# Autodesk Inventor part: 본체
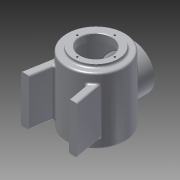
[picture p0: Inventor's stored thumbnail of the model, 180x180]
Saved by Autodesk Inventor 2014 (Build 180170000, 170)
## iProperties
Created: 2015-01
Part Number: 본체
Material: 알루미늄 6061
Document SubType Name: Modeling
Designer: Administrator
Density: 2.71 g/cm^3
Appearance: 알루미늄 - 평지
Mass: 1021.13 g
Surface Area: 1060.37 cm^2
Volume: 376.8 cm^3
Author: Administrator
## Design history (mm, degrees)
sketch "스케치1"
  geometry: L1 (-34, -80)-(-27.282, -41.901); L2 (-48, -80)-(-39.336, -30.865); L3 (-48, -80)-(-34, -80); L4 (0, 50)-(0, -50); A1 r 50 centre (0, 0) between (0, 50) and (-39.336, -30.865); A2 r 50 centre (0, 0) between (-27.282, -41.901) and (0, -50); 1 further point
  constraints: 8 end point, 4 point on circle, 2 centre point, 1 coincident, 1 horizontal, 1 parallel, 1 perpendicular
  dimensions: "d8" = 50 radius of A2; "d9" = 50 radius of A1; "d12" = 13.78731 distance between parallel lines of L1 L2; "d15" = 19.59161 distance from line of point (0, 0) L1; "d16" = 80 distance from line of point (0, 0) L3; "d33" = 10 deg angle of L4 L1; "d34" = 0 distance from line of point (0, 0) L4
extrude "돌출1" new body sketch "스케치1" distance "d17" = 40; taper "d18" = 0 deg
sketch "스케치7"
  geometry: L1 (0, -50)-(0, 50) reference; L2 (0, 50)-(0, -50); A1 r 50 centre (0, 0) between (0, 50) and (-39.336, -30.865) reference; A2 r 50 centre (0, 0) between (0, 50) and (0, -50)
  constraints: 2 end point, 2 point on circle, 1 centre point, 1 coincident, 1 collinear
extrude "돌출6" join sketch "스케치7" distance "d36" = 16; taper "d37" = 0 deg
sketch "스케치8"
  geometry: L1 (-34, 30)-(-34, 130) reference; A1 r 50 centre (-34, 80) between (-34, 30) and (-34, 130) reference
extrude "돌출7" join sketch "스케치8" distance "d38" = 16; taper "d39" = 0 deg
sketch "스케치9"
  geometry: L1 (0, -50)-(0, 50) reference; A1 r 50 centre (0, 0) between (0, 50) and (0, -50) reference; A2 r 38 centre (0, 0) between (0, 38) and (0, -38)
  constraints: 2 point on circle, 2 point on line, 1 centre point, 1 coincident
  dimensions: "d40" = 76 diameter of A2
extrude "돌출8" join sketch "스케치9" distance "d41" = 5; taper "d42" = 0 deg
sketch "스케치10"
  geometry: L1 (-34, 42)-(-34, 118) reference; A1 r 38 centre (-34, 80) between (-34, 42) and (-34, 118) reference
extrude "돌출9" join sketch "스케치10" distance "d43" = 5; taper "d44" = 0 deg
sketch "스케치11"
  geometry: L1 (30, -44)-(84, -44); L2 (30, -56)-(84, -56); L3 (84, -44)-(84, -56); L4 (30, -44)-(30, -56); 1 further point
  constraints: 8 end point
  dimensions: "d46" = 54 distance between parallel lines of L3 L4; "d48" = 12 distance between parallel lines of L2 L1
extrude "돌출10" join sketch "스케치11" distance "d50" = 52; taper "d51" = 0 deg
sketch "스케치12"
  geometry: C1 r 38 at (0, 1); 2 further points
  constraints: 1 centre point
  dimensions: "d53" = 76 diameter of C1
extrude "돌출11" join sketch "스케치12" distance "d54" = 62; taper "d55" = 0 deg
sketch "스케치13"
  geometry: C1 r 38 at (0, 0) reference; C2 r 27 at (0, 0)
  constraints: 1 centre point, 1 coincident
  dimensions: "d56" = 54 diameter of C2
extrude "돌출12" cut sketch "스케치13" distance "d57" = 12; taper "d58" = 0 deg
sketch "스케치14"
  geometry: C1 r 38 at (0, 0) reference; C2 r 27 at (0, 0)
  constraints: 1 centre point, 1 coincident
  dimensions: "d59" = 54 diameter of C2
extrude "돌출13" cut sketch "스케치14" distance "d60" = 13; taper "d61" = 0 deg
sketch "스케치15"
  geometry: C1 r 27 at (0, 0) reference; C2 r 45 at (0, 0)
  constraints: 1 centre point, 1 coincident
  dimensions: "d62" = 90 diameter of C2
extrude "돌출14" cut sketch "스케치15" distance "d63" = 97; taper "d64" = 0 deg
sketch "스케치16"
  geometry: C1 r 5.108 at (0, 32)
  constraints: 1 centre point
hole "구멍1" sketch "스케치16" at (0, 32) diameter "d66" = 3.242; stored, may be unused: countersink angle "d70" = 90 deg, drill point angle "d72" = 118 deg; dims "d67" = 8, "d68" = 4, "d69" = 2, "d71" = 10
sketch "스케치17"
  geometry: C1 r 1.621 at (0, 32) reference
hole "구멍2" sketch "스케치17" at (0, 32) diameter "d76" = 3.242; stored, may be unused: countersink angle "d80" = 90 deg, drill point angle "d82" = 118 deg; dims "d77" = 8, "d78" = 4, "d79" = 2, "d81" = 10
sketch "스케치20"
  geometry: L1 (-80.68, -46.398)-(-30.905, -46.398); L2 (-30.905, -46.398)-(-30.905, -53.602); L3 (-30.905, -53.602)-(-80.68, -53.602); L4 (-80.68, -53.602)-(-80.68, -46.398); 1 further point
  constraints: 2 other
feature "엠보싱1" sketch "스케치20" dims "d8" = 50, "d9" = 50, "d12" = 13.78731, "d15" = 19.59161, "d16" = 80, "d33" = 10 deg, "d34" = 0, "d100" = 0.5, "d101" = 0
chamfer "모따기1" distance "d102" = 1; stored, may be unused: second distance "d103" = 2, angle "d104" = 45 deg
chamfer "모따기2" distance "d105" = 1; stored, may be unused: second distance "d106" = 2, angle "d107" = 45 deg
fillet "모깎기1" dims "d111" = 3
fillet "모깎기2" dims "d112" = 3
fillet "모깎기3" dims "d113" = 3
sketch "스케치22"
  geometry: C1 r 38 at (0, 0) reference; C2 r 27 at (0, 0); 1 further point
  constraints: 1 centre point
  dimensions: "d115" = 54 diameter of C2
extrude "돌출16" cut sketch "스케치22" distance "d116" = 30; taper "d117" = 0 deg
sketch "스케치23"
  geometry: C1 r 2.093 at (0, 32); 1 further point
  constraints: 1 centre point
hole "구멍4" sketch "스케치23" at (0, 32) diameter "d119" = 3.242; stored, may be unused: countersink angle "d123" = 90 deg, drill point angle "d125" = 118 deg; dims "d120" = 6, "d121" = 4, "d122" = 2, "d124" = 8
chamfer "모따기4" distance "d129" = 1; stored, may be unused: second distance "d130" = 2, angle "d131" = 45 deg
fillet "모깎기4" dims "d132" = 3
node "솔리드1"
mirror "대칭2"
mirror "대칭3"
pattern_circular "원형 패턴1" dims angle "d74" = 360 deg
pattern_circular "원형 패턴2" dims angle "d84" = 360 deg
pattern_circular "원형 패턴4" dims angle "d127" = 360 deg
node "투영된 루프2"
node "투영된 루프3"
